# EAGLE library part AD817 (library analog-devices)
High Speed, Low Power Wide Supply Range Amplifier Source: http://www.analog.com/static/imported-files/data_sheets/AD817.pdf
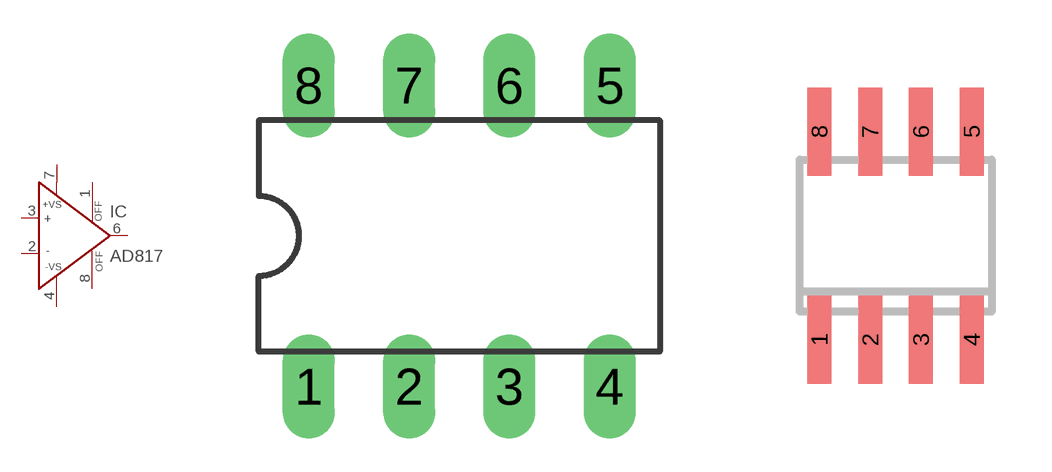
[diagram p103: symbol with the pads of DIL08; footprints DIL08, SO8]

Designator prefix IC

## AD817N (OC_FARNELL: 9604006; OC_NEWARK: unknown)  [DIL08]
1  OFF  pas
2  IN-  in
3  IN+  in
4  -VS  in
6  OUT  out
7  +VS  in
8  OFF  pas

## AD817 (MF: ALTERA CORPORATION; MPN: AD817ARZ; OC_FARNELL: 1660992; OC_NEWARK: 88H0179)  [SO8]
Pads as for DIL08

## Footprint DIL08 (pad centres in mm)
Dual In Line Package
drill 0.813 long: 1 -3.81,-3.81; 2 -1.27,-3.81; 3 1.27,-3.81; 4 3.81,-3.81; 5 3.81,3.81; 6 1.27,3.81; 7 -1.27,3.81; 8 -3.81,3.81

## Footprint SO8 (pad centres in mm)
8-Lead Small Outline IC (SO-8) Source: http://www.analog.com/UploadedFiles/Data_Sheets/703465986AD8611_2_0.pdf
smd 0.6 x 2.2: 1 -1.905,-2.6; 2 -0.635,-2.6; 3 0.635,-2.6; 4 1.905,-2.6; 5 1.905,2.6; 6 0.635,2.6; 7 -0.635,2.6; 8 -1.905,2.6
